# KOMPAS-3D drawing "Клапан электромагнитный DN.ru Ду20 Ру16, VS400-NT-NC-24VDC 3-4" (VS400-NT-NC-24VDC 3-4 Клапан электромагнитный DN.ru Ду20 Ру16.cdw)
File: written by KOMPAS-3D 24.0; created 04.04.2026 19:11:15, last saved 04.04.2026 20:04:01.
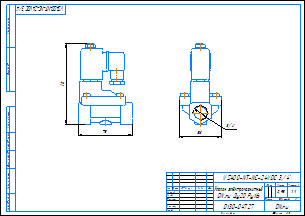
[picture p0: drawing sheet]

Document properties: c3d_UniqueCompID: ef56311e-7521-43dc-8291-0e6108b3d81d; Обозначение: VS400-ET-NC-220VAC 1-2; Наименование: Клапан электромагнитный DN.ru Ду15 Ру16; Автор: artio; Класс точности: c; Знак неуказанной шероховатости: Шероховатость не задана; Рассекать на разрезах: Да; c3d_UniqueCompID: ef56311e-7521-43dc-8291-0e6108b3d81d; Обозначение: VS400-ET-NC-220VAC 3-4; Наименование: Клапан электромагнитный DN.ru Ду20 Ру16; Автор: artio; Класс точности: c; Знак неуказанной шероховатости: Шероховатость не задана; Рассекать на разрезах: Да; c3d_UniqueCompID: ef56311e-7521-43dc-8291-0e6108b3d81d; Обозначение: VS400-ET-NC-220VAC 3-8; Наименование: Клапан электромагнитный DN.ru Ду10 Ру16; Автор: artio; Класс точности: c; Знак неуказанной шероховатости: Шероховатость не задана; Рассекать на разрезах: Да; Автор: artio; Форматы листов документа: A3; Полное имя файла: VS400-NT-NC-24VDC 3-4 Клапан электромагнитный DN.ru Ду20 Ру16.m3d; Масса: 0.954; Наименование: Клапан электромагнитный DN.ru Ду20 Ру16; Количество листов документа: 1; Примечание: D130-04727

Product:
- Body: Тело 1  | qty 1
    Масса: 1.210539
- Part/product: Клапан электромагнитный DN.ru Ду20 Ру16  | designation VS400-NT-NC-24VDC 3-4
    Масса: 0.954
    Раздел спецификации: Прочие изделия
    Примечание: D130-04727
    additional columns: ef56311e-7521-43dc-8291-0e6108b3d81d; VS400-ET-NC-220VAC 3-4; artio; c; Шероховатость не задана; Да

Views: Вид 1, Спереди, Проекционный вид 2
Referenced files in C:\Users\artio\OneDrive\Рабочий стол\Клапан электромагнитный DN.ru\VS400-ET-NC\VS400-ET-NC-24VDC\: VS400-ET-NC-24VDC 3-8 Клапан электромагнитный DN.ru Ду10 Ру16.m3d
Referenced files in C:\Users\artio\OneDrive\Рабочий стол\Клапан электромагнитный DN.ru\VS400-NT-NC\VS400-NT-NC-24VDC\: VS400-NT-NC-24VDC 3-4 Клапан электромагнитный DN.ru Ду20 Ру16.m3d
Referenced files in C:\Users\artio\OneDrive\Рабочий стол\Клапан электромагнитный DN.ru\VS400-ET-NC\: VS400-ET-NC-24VDC 3-8 Клапан электромагнитный DN.ru Ду10 Ру16.cdw
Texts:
  VS400-NT-NC-24VDC 3-4
  Клапан электромагнитный
  DN.ru Ду20 Ру16
  VS400-NT-NC-24VDC 3/4"
  VS400-NT-NC-24VDC 3/4"-
  Клапан электромагнитный DN.ru Ду20 Ру16
  VS400-NT-NC-24VDC 3-4 Клапан электромагнитный DN.ru Ду20 Ру16
Dimensions and other numbers on the sheet: 0; 3; 2; 4; 58; 3/4"; 75; 112; 1:1; 1; 0,95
